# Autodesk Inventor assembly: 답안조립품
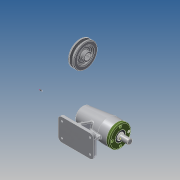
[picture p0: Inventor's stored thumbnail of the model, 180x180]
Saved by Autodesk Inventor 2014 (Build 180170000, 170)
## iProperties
Created: 2018-09
Part Number: 답안조립품
Document SubType Name: Assembly
Designer: kb542
Author: kb542
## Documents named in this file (12)
- C:\Users\kb542\Desktop\480907V1009\답안조립품.iam
- C:\Users\kb542\Desktop\480907V1009\본체.ipt
- C:\Users\kb542\Desktop\480907V1009\V벨트풀리.ipt
- C:\Users\kb542\Desktop\480907V1009\멈춤나사 M3.ipt
- C:\Users\kb542\Desktop\480907V1009\베어링 6004.ipt
- C:\Users\kb542\Desktop\480907V1009\베어링 51202.ipt
- C:\Users\kb542\Desktop\480907V1009\볼트 M4.ipt
- C:\Users\kb542\Desktop\480907V1009\어댑터슬리브.ipt
- C:\Users\kb542\Desktop\480907V1009\오일 실.ipt
- C:\Users\kb542\Desktop\480907V1009\축.ipt
- C:\Users\kb542\Desktop\480907V1009\커버.ipt
- C:\Users\kb542\Desktop\480907V1009\키 5 x 5 x 16.ipt
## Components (1 placed, 1 different names)
1. V벨트풀리:1
